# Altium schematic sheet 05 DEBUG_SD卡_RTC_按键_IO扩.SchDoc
size 297 x 209 mm
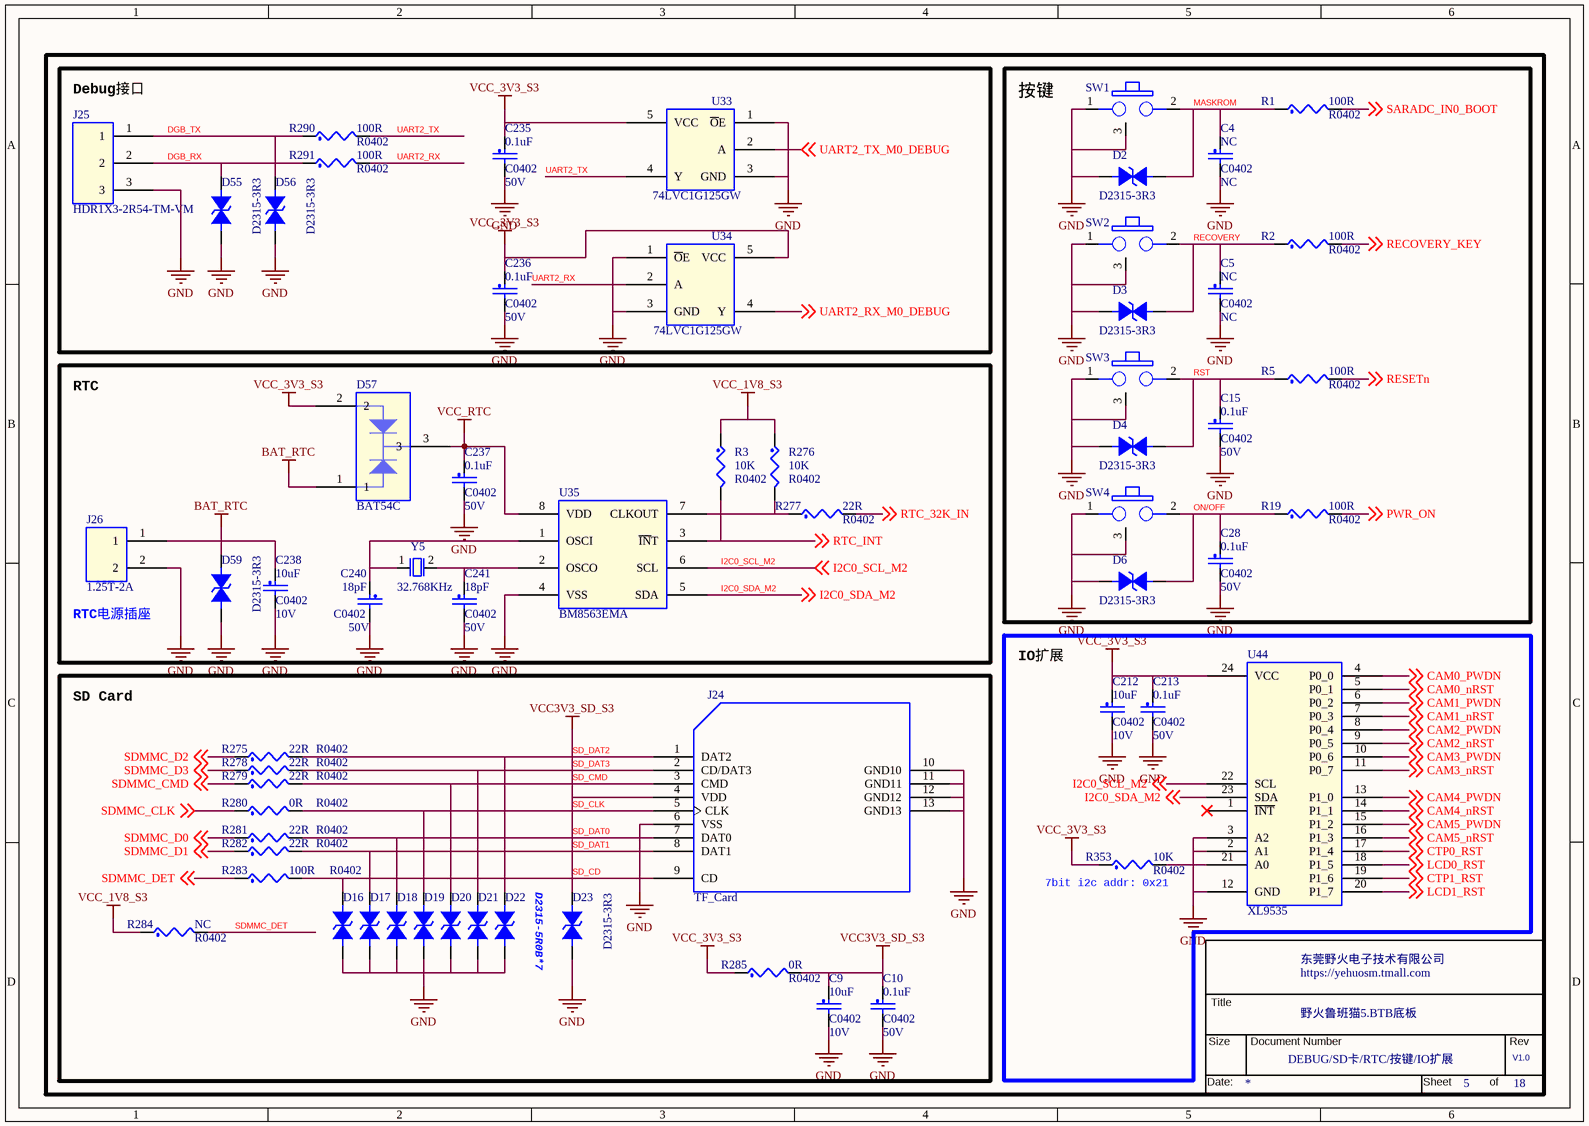
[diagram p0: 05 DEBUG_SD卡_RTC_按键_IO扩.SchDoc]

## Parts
*  Doc: DEBUG/SD卡/RTC/按键/IO扩展  RevCode: V1.0  Title: 野火鲁班猫5.BTB底板  OrgName: 东莞野火电子技术有限公司  Page Number: 5  Page Count: 18  (hidden comment: TitleBlock_YHSCH)  (graphical)
C4  NC  [C0402]
C5  NC  [C0402]
C9  10uF  Voltage: 10V  [C0402]
C10  0.1uF  Voltage: 50V  [C0402]
C15  0.1uF  Voltage: 50V  [C0402]
C28  0.1uF  Voltage: 50V  [C0402]
C212  10uF  Voltage: 10V  [C0402]
C213  0.1uF  Voltage: 50V  [C0402]
C235  0.1uF  Voltage: 50V  [C0402]
C236  0.1uF  Voltage: 50V  [C0402]
C237  0.1uF  Voltage: 50V  [C0402]
C238  10uF  Voltage: 10V  [C0402]
C240  18pF  Voltage: 50V  [C0402]
C241  18pF  Voltage: 50V  [C0402]
D2  D2315-3R3  [D0603/SMD]
D3  D2315-3R3  [D0603/SMD]
D4  D2315-3R3  [D0603/SMD]
D6  D2315-3R3  [D0603/SMD]
D16  D2315-5R0B  [D0603/SMD]  (value not drawn)
D17  D2315-5R0B  [D0603/SMD]  (value not drawn)
D18  D2315-5R0B  [D0603/SMD]  (value not drawn)
D19  D2315-5R0B  [D0603/SMD]  (value not drawn)
D20  D2315-5R0B  [D0603/SMD]  (value not drawn)
D21  D2315-5R0B  [D0603/SMD]  (value not drawn)
D22  D2315-5R0B  [D0603/SMD]  (value not drawn)
D23  D2315-3R3  [D0603/SMD]
D55  D2315-3R3  [D0603/SMD]
D56  D2315-3R3  [D0603/SMD]
D57  BAT54C  [SOT23]
D59  D2315-3R3  [D0603/SMD]
J24  TF_Card  [TFCARD]
J25  HDR1X3-2R54-TM-VM  [HDR1X3-2R54-TM-VM]
J26  1.25T-2A  [gh1p25_th_2p]
R1  100R  [R0402]
R2  100R  [R0402]
R3  10K  [R0402]
R5  100R  [R0402]
R19  100R  [R0402]
R275  22R  [R0402]
R276  10K  [R0402]
R277  22R  [R0402]
R278  22R  [R0402]
R279  22R  [R0402]
R280  0R  [R0402]
R281  22R  [R0402]
R282  22R  [R0402]
R283  100R  [R0402]
R284  NC  [R0402]
R285  0R  [R0402]
R290  100R  [R0402]
R291  100R  [R0402]
R353  10K  [R0402]
SW1  TS-1091B-A5B3-D2  [sw_th_3p_4r5x5r5]  (value not drawn)
SW2  TS-1091B-A5B3-D2  [sw_th_3p_4r5x5r5]  (value not drawn)
SW3  TS-1091B-A5B3-D2  [sw_th_3p_4r5x5r5]  (value not drawn)
SW4  TS-1091B-A5B3-D2  [sw_th_3p_4r5x5r5]  (value not drawn)
U33  74LVC1G125GW  [SOT-353]
U34  74LVC1G125GW  [SOT-353]
U35  BM8563EMA  [msop-8]
U44  XL9535  [TSSOP24-0R65-7R80X4R40]
Y5  32.768KHz  [3215]

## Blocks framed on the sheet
Debug接口: C235 C236 D55 D56 J25 R290 R291 U33 U34
按键: C4 C5 C15 C28 D2-D4 D6 R1 R2 R5 R19 SW1-SW4
RTC: C237 C238 C240 C241 D57 D59 J26 R3 R276 R277 U35 Y5
IO扩展: C212 C213 R353 U44
SD Card: C9 C10 D16-D23 J24 R275 R278-R285

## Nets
BAT_RTC: C238.1 D57.1 D59.1 J26.1
GND: C4.2 C5.2 C9.2 C10.2 C15.2 C28.2 C212.2 C213.2 C235.2 C236.2 C237.2 C238.2 C240.2 C241.2 D2.1 D3.1 D4.1 D6.1 D16.1 D17.1 D18.1 D19.1 D20.1 D21.1 D22.1 D23.2 D55.2 D56.2 D59.2 J24.6(VSS) J24.10(GND10) J24.11(GND11) J24.12(GND12) J24.13(GND13) J25.3 J26.2 SW1.1(A1) SW1.3(GND1) SW2.1(A1) SW2.3(GND1) SW3.1(A1) SW3.3(GND1) SW4.1(A1) SW4.3(GND1) U33.1(~{O}E) U33.3(GND) U34.1(~{O}E) U34.3(GND) U35.4(VSS) U44.2(A1) U44.3(A2) U44.12(GND)
SD_CD: C9.1 C10.1 D16.2 D17.2 D18.2 D19.2 D20.2 D21.2 D22.2 D23.1 J24.1(DAT2) J24.2(CD/DAT3) J24.3(CMD) J24.4(VDD) J24.5(CLK) J24.7(DAT0) J24.8(DAT1) J24.9(CD) R275.2 R278.2 R279.2 R280.2 R281.2 R282.2 R283.2 R285.2  [also labelled SD_CLK, SD_CMD, SD_DAT0, SD_DAT1, SD_DAT2, SD_DAT3, VCC3V3_SD_S3]
VCC_1V8_S3: R3.1 R276.1 R284.1
VCC_3V3_S3: C212.1 C213.1 C235.1 C236.1 D57.2 R285.1 R353.1 U33.5(VCC) U34.5(VCC) U44.24(VCC)
VCC_RTC: C237.1 D57.3 U35.8(VDD)
CAM0_nRST: U44.5(P0_1) ; off-sheet CAM0_nRST
CAM0_PWDN: U44.4(P0_0) ; off-sheet CAM0_PWDN
CAM1_nRST: U44.7(P0_3) ; off-sheet CAM1_nRST
CAM1_PWDN: U44.6(P0_2) ; off-sheet CAM1_PWDN
CAM2_nRST: U44.9(P0_5) ; off-sheet CAM2_nRST
CAM2_PWDN: U44.8(P0_4) ; off-sheet CAM2_PWDN
CAM3_nRST: U44.11(P0_7) ; off-sheet CAM3_nRST
CAM3_PWDN: U44.10(P0_6) ; off-sheet CAM3_PWDN
CAM4_nRST: U44.14(P1_1) ; off-sheet CAM4_nRST
CAM4_PWDN: U44.13(P1_0) ; off-sheet CAM4_PWDN
CAM5_nRST: U44.16(P1_3) ; off-sheet CAM5_nRST
CAM5_PWDN: U44.15(P1_2) ; off-sheet CAM5_PWDN
CTP0_RST: U44.17(P1_4) ; off-sheet CTP0_RST
CTP1_RST: U44.19(P1_6) ; off-sheet CTP1_RST
DGB_RX: D55.1 J25.2 R291.1
DGB_TX: D56.1 J25.1 R290.1
I2C0_SCL_M2: U35.6(SCL) U44.22(SCL) ; off-sheet I2C0_SCL_M2
I2C0_SDA_M2: U35.5(SDA) U44.23(SDA) ; off-sheet I2C0_SDA_M2
LCD0_RST: U44.18(P1_5) ; off-sheet LCD0_RST
LCD1_RST: U44.20(P1_7) ; off-sheet LCD1_RST
MASKROM: C4.1 D2.2 R1.1 SW1.2(B1)
ON/OFF: C28.1 D6.2 R19.1 SW4.2(B1)
PWR_ON: R19.2 ; off-sheet PWR_ON
RECOVERY: C5.1 D3.2 R2.1 SW2.2(B1)
RECOVERY_KEY: R2.2 ; off-sheet RECOVERY_KEY
RESETn: R5.2 ; off-sheet RESETn
RST: C15.1 D4.2 R5.1 SW3.2(B1)
RTC_32K_IN: R277.2 ; off-sheet RTC_32K_IN
RTC_INT: R3.2 U35.3(~{IN}T) ; off-sheet RTC_INT
SARADC_IN0_BOOT: R1.2 ; off-sheet SARADC_IN0_BOOT
SDMMC_CLK: R280.1 ; off-sheet SDMMC_CLK
SDMMC_CMD: R279.1 ; off-sheet SDMMC_CMD
SDMMC_D0: R281.1 ; off-sheet SDMMC_D0
SDMMC_D1: R282.1 ; off-sheet SDMMC_D1
SDMMC_D2: R275.1 ; off-sheet SDMMC_D2
SDMMC_D3: R278.1 ; off-sheet SDMMC_D3
SDMMC_DET: R283.1 R284.2 ; off-sheet SDMMC_DET
UART2_RX: R291.2 U34.2(A)
UART2_RX_M0_DEBUG: U34.4(Y) ; off-sheet UART2_RX_M0_DEBUG
UART2_TX: R290.2 U33.4(Y)
UART2_TX_M0_DEBUG: U33.2(A) ; off-sheet UART2_TX_M0_DEBUG
NetC240_1: C240.1 U35.1(OSCI) Y5.1
NetC241_1: C241.1 U35.2(OSCO) Y5.2
NetR276_2: R276.2 R277.1 U35.7(CLKOUT)
NetR353_2: R353.2 U44.21(A0)

Not connected (* = marked no-connect by the designer): U44 1(~{INT})*

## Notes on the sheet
- (near J26) RTC电源插座
- D2315-5R0B*7
- (near R353) 7bit i2c addr: 0x21

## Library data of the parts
* = TitleBlock_YHSCH: Cage Code: 1
C4 = CAP_NP: CLASS: DISCRETE; 类别: 贴片电容0402; 条码: EBF29060149; 规格: 贴片电容NC 预留
C5 = CAP_NP: CLASS: DISCRETE; 规格: 贴片电容NC 预留; 条码: EBF29060149; 类别: 贴片电容0402
C9 C212 C238 = CAP_NP: CLASS: DISCRETE; 生命周期: 量产; 价格: 0.518415; 规格书: 三星电容.pdf; 类别: 贴片电容0402; 品牌: 三星; 条码: EBF29060247; 规格编号: CL05A106MP8NUB8; 规格: 贴片电容10uF 20% 10V X5R 0402
C10 C15 C28 C213 C236 = CAP_NP: CLASS: DISCRETE; 生命周期: 量产; 价格: 0.029826; 规格书: 风华电容.pdf; 类别: 贴片电容0402; 品牌: 风华; 条码: EBF29060118; 规格编号: 0402X104K500NT; 规格: 贴片电容0.1uF 10% 50V X5R 0402
C235 C237 = CAP_NP: CLASS: DISCRETE; 规格: 贴片电容0.1uF 10% 50V X5R 0402; 规格编号: 0402X104K500NT; 条码: EBF29060118; 品牌: 风华; 类别: 贴片电容0402; 规格书: 风华电容.pdf; 价格: 0.029826; 生命周期: 量产
C240 C241 = CAP_NP: CLASS: DISCRETE; 规格: 贴片电容18pF 5% 50V C0G 0402; 规格编号: 0402CG180J500NT; 条码: EBF29060235; 品牌: 风华; 类别: 贴片电容0402; 规格书: 风华电容.pdf; 价格: 0.00515; 生命周期: 量产
D2-D4 D6 D23 D56 D59 = DIODE BI-DIR TRIG: PCB Footprint: esd0402; 生命周期: 量产; 规格书: 千虹_D2315-3R3.pdf; 类别: 贴片ESD; 品牌: 千虹; 条码: EBFCIS240517170749; 规格: 防静电保护ESD二极管 反向工作电压3.3V 击穿电压3.5V 钳位电压9V 结电容Cj 10pF; 备注: 通用
D16-D22 = DIODE BI-DIR TRIG: PCB Footprint: esd0402; 备注: 通用; 生命周期: 量产; 规格书: 千虹_D2315-5R0B.pdf; 类别: 贴片ESD; 品牌: 千虹; 条码: EBFCIS240517170922; 规格: 防静电保护ESD二极管 反向工作电压5V 击穿电压7V 钳位电压10.5V 结电容Cj 0.3pF
D55 = DIODE BI-DIR TRIG: 备注: 通用; 规格: 防静电保护ESD二极管 反向工作电压3.3V 击穿电压3.5V 钳位电压9V 结电容Cj 10pF; 条码: EBFCIS240517170749; 品牌: 千虹; 类别: 贴片ESD; 规格书: 千虹_D2315-3R3.pdf; 生命周期: 量产; PCB Footprint: esd0402
D57 = BAT54C: 规格: 肖特基双二极管 直流反向耐压(Vr) 30V 平均整流电流(Io) 300mA 正向压降(Vf) 1V@100mA; 条码: EBF29140062; 品牌: 江苏长电; 类别: 贴片肖特基二极管; 规格书: 江苏长电_BAT54C.pdf; 价格: 0.077486; 生命周期: 量产; 丝印: KL3
J24 = TF_Card: CLASS: IO; 可替代料: EBF29040003; 生命周期: 量产; 价格: 0.48; 规格书: 硕方-TF-015.pdf; 类别: SD卡连接器; 品牌: 硕方; 规格编号: TF-015; 规格: MICRO SD 卡座 TF T-Flash 外焊 双压片 自弹贴片
J25 = 1X3PIN: 价格: 0.06; 品牌: 州日; 规格编号: HDR1X3-2R54-TM-VM-BLUE; 规格书: 州日_单排针_直插_2P54.pdf; 生命周期: 量产; 类别: 2.54mm直插单排排针; 条码: EBF29020046; 规格: 蓝色直插单排排针 总PIN数3 间距2.54mm
J26 = 1X2PIN: 生命周期: 量产; 规格书: 1.25T-2A.pdf; 类别: 1.25连接器; 品牌: 创都; 条码: EBF29040105; 规格: 间距=1.25mm 直插 2P针座连接器
R1 = RES: CLASS: DISCRETE; 生命周期: 量产; 规格书: 合科泰-RI系列电阻.pdf; 类别: 贴片电阻0402; 品牌: 合科泰; 条码: EBF29070053; 规格编号: RI0402L1000FT; 规格: 贴片电阻100R 1% 1/16W 0402
R2 R5 R19 R283 R290 R291 = RES: CLASS: DISCRETE; 规格: 贴片电阻100R 1% 1/16W 0402; 规格编号: RI0402L1000FT; 条码: EBF29070053; 品牌: 合科泰; 类别: 贴片电阻0402; 规格书: 合科泰-RI系列电阻.pdf; 生命周期: 量产
R3 R276 R353 = RES: CLASS: DISCRETE; 生命周期: 量产; 价格: 0.002773; 规格书: 厚声-无铅厚膜电阻.pdf; 类别: 贴片电阻0402; 品牌: 厚声; 条码: EBF29070046; 规格编号: 0402WGF1002TCE; 规格: 贴片电阻10K 1% 1/16W 0402
R275 R277-R279 R281 R282 = RES: CLASS: DISCRETE; 规格: 贴片电阻22R 1% 1/16W 0402; 规格编号: RI0402L22R0FT; 条码: EBF29070181; 品牌: 合科泰; 类别: 贴片电阻0402; 规格书: 合科泰-RI系列电阻.pdf; 生命周期: 量产
R280 = RES: CLASS: DISCRETE; 规格: 贴片电阻0R 1% 1/16W 0402; 规格编号: RI0402L000FT; 条码: EBF29070049; 品牌: 合科泰; 类别: 贴片电阻0402; 规格书: 合科泰-RI系列电阻.pdf; 生命周期: 量产
R284 = RES: CLASS: DISCRETE; 类别: 贴片电阻0402; 条码: EBF29070087; 规格: 贴片电阻NC 预留
R285 = RES: CLASS: DISCRETE; 生命周期: 量产; 规格书: 合科泰-RI系列电阻.pdf; 类别: 贴片电阻0402; 品牌: 合科泰; 条码: EBF29070049; 规格编号: RI0402L000FT; 规格: 贴片电阻0R 1% 1/16W 0402
SW1 = SW_TH3P: CLASS: IC; 价格: 0.249174; 生命周期: 量产; 规格书: 轻触开关4.5_4.5_5.5边三脚侧插侧按按键254GF.pdf; 类别: 直插按键; 品牌: 台湾元迪; 条码: EBF29310018; 规格: 轻触开关4.5_4.5_5.5边三脚侧插侧按按键254GF
SW2 = SW_TH3P: CLASS: IC; 规格: 轻触开关4.5_4.5_5.5边三脚侧插侧按按键254GF; 条码: EBF29310018; 品牌: 台湾元迪; 类别: 直插按键; 规格书: 轻触开关4.5_4.5_5.5边三脚侧插侧按按键254GF.pdf; 生命周期: 量产; 价格: 0.249174
SW3 SW4 = SW_TH3P: CLASS: IC; 生命周期: 量产; 规格书: 轻触开关4.5_4.5_5.5边三脚侧插侧按按键254GF.pdf; 类别: 直插按键; 品牌: 台湾元迪; 条码: EBF29310018; 规格: 轻触开关4.5_4.5_5.5边三脚侧插侧按按键254GF; 价格: 0.249174
U33 U34 = 74LVC1G125: 丝印: VM; 生命周期: 量产; 价格: 0.182409; 规格书: 74LVC1G125GW.pdf; 类别: 隔离器件; 品牌: 安世; 条码: EBF29170001; 规格: 时钟缓冲器 驱动器 具有三态输出 允许工作电压为3.3V 5.5V 典型工作电流100mA
U35 = HYM8563S: 生命周期: 量产; 价格: 0.8789; 规格书: 捷茂微_BM8563EMA.pdf; 类别: 实时时钟芯片; 品牌: 捷茂微; 条码: EBFCIS240229100017; 规格: 工作电压1.5V~5.5V 日期格式YY-MM-DD 时间格式HH:MM:SS 接口类型I2C 电流消耗0.25uA~@3.0V; 备注: 鲁班猫系列板子
U44 = XL9535: 丝印: XL9535D; 备注: RK3588 BTB底板; 生命周期: 量产; 价格: 1.75; 规格书: 信路达_XL9535.pdf; 类别: IO拓展; 品牌: 信路达; 条码: EBFCIS230803102100; 规格: I2C接口 16个双向输入输出引脚 支持中断输出 工作电压2.3V~5.5V
Y5 = CRYSTAL_2P: 生命周期: 量产; 价格: 2.57; 规格书: 爱普生-32.768KHz.pdf; 类别: 贴片晶振 3215; 品牌: 爱普生; 条码: EBF29100004; 规格编号: Q13FC1350000300; 规格: 无源晶振32.768KHz 70KΩ 9pF 3215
